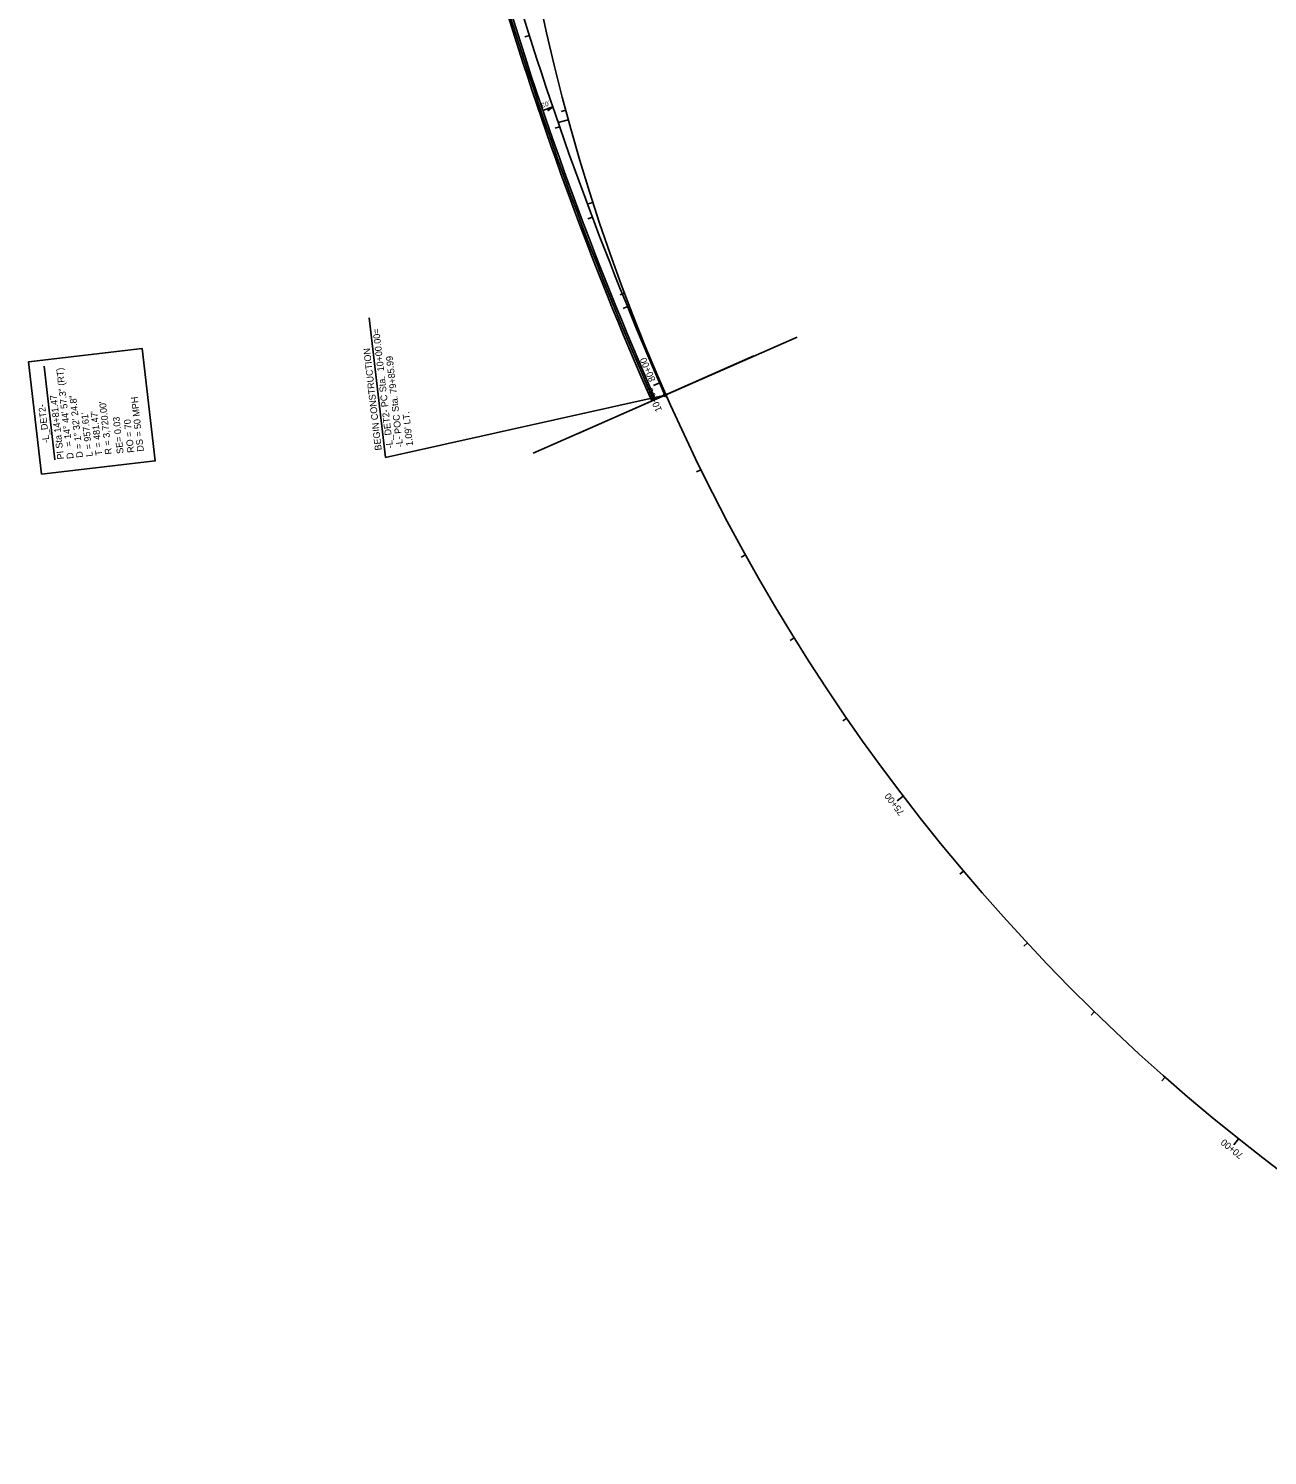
# Model space of a CAD drawing. Extents: x 473658 to 481584, y 489119 to 506230.
# Drawn here: x 477916 to 479205, y 493541 to 495025 of the extents above; entities that cross this region are included whole.
import ezdxf

# ---------------------------------------------------------------- set-up
doc = ezdxf.new("R2010")
doc.units = 0
for name, color, linetype in [('Prop EOT', 7, 'Continuous'), ('Prop Grid Mask', 7, 'Continuous'), ('Prop Horizontal Alignment', 7, 'Continuous'), ('Prop Horizontal Alignment Curve and Spiral Data', 7, 'Continuous'), ('Prop Horizontal Alignment Station Label', 7, 'Continuous'), ('Prop Horizontal Alignment Tick Label', 7, 'Continuous'), ('Prop Horizontal Alignment Tick Large', 7, 'Continuous'), ('Prop Horizontal Alignment Tick Small', 7, 'Continuous'), ('Prop Paved Shoulder', 7, 'Continuous'), ('Prop Superelevation  Arrow CELL', 7, 'Continuous'), ('Prop Superelevation Label', 7, 'Continuous'), ('Scratch_Level_3', 7, 'Continuous'), ('Scratch_Level_4', 7, 'Continuous'), ('Scratch_Level_5', 7, 'Continuous'), ('Scratch_Level_6', 7, 'Continuous'), ('Scratch_Level_9', 7, 'Continuous')]:
    doc.layers.add(name, color=color, linetype=linetype)

msp = doc.modelspace()

# ---------------------------------------------------------------- linework, layer by layer
at = {"layer": 'Prop EOT'}
msp.add_arc((481983.3, 496141.9), 3731, 188.9925, 203.7418, dxfattribs=at)
at = {"layer": 'Prop Grid Mask'}
msp.add_lwpolyline([(477929.8, 494562), (477916.3, 494678.9), (478034.6, 494692.6), (478048.1, 494575.7)], close=True, dxfattribs=at)
at = {"layer": 'Prop Horizontal Alignment'}
for centre, radius, start, end in [((481983.3, 496141.9), 3720, 188.9925, 203.7418), ((480454.8, 495471.8), 2050, 189.8162, 250.3298)]:
    msp.add_arc(centre, radius, start, end, dxfattribs=at)
at = {"layer": 'Prop Horizontal Alignment Station Label'}
for p, q in [((478287.4, 494579.4), (478270.6, 494724.7)), ((477932.4, 494674.2), (477943.7, 494576.8)), ((477932.4, 494674.2), (477943.7, 494576.8)), ((478578.2, 494644.1), (478287.4, 494579.4))]:
    msp.add_line(p, q, dxfattribs=at)
msp.add_circle((478578.2, 494644.1), 1.5, dxfattribs=at)
msp.add_circle((478578.2, 494644.1), 1.5, dxfattribs=at)
at = {"layer": 'Prop Horizontal Alignment Tick Large'}
for p, q in [((478573.6, 494657.4), (478566.2, 494654.2)), ((478578.2, 494644.1), (478570.9, 494640.9)), ((478825.9, 494227.2), (478819.6, 494222.3)), ((479174.7, 493870.7), (479169.7, 493864.4))]:
    msp.add_line(p, q, dxfattribs=at)
at = {"layer": 'Prop Horizontal Alignment Tick Small'}
for p, q in [((478437.1, 495018.2), (478432.3, 495016.7)), ((478474.9, 494940.4), (478470.1, 494939.1)), ((478468.6, 494923.3), (478463.9, 494921.7)), ((478503.2, 494844.5), (478498.4, 494843)), ((478502.6, 494829.3), (478497.9, 494827.5)), ((478536.1, 494750.1), (478531.4, 494748.3)), ((478539.1, 494736.2), (478534.5, 494734.3)), ((478615.5, 494566.6), (478611, 494564.4)), ((478661.8, 494478), (478657.5, 494475.6)), ((478712.4, 494391.8), (478708.2, 494389.1)), ((478767.2, 494308.1), (478763.1, 494305.3)), ((478888.6, 494149.2), (478884.7, 494146)), ((478954.9, 494074.4), (478951.2, 494071)), ((479024.8, 494003), (479021.3, 493999.4)), ((479098.2, 493935), (479094.8, 493931.2))]:
    msp.add_line(p, q, dxfattribs=at)
at = {"layer": 'Prop Paved Shoulder'}
msp.add_arc((481983.3, 496141.9), 3733, 194.2248, 203.7418, dxfattribs=at)
at = {"layer": 'Prop Superelevation  Arrow CELL'}
msp.add_lwpolyline([(478461.5, 494943.8), (478456.5, 494940), (478457.2, 494942.4)], close=True, dxfattribs=at)
at = {"layer": 'Prop Superelevation Label'}
msp.add_line((478451.1, 494940.3), (478461.5, 494943.8), dxfattribs=at)
at = {"layer": 'Scratch_Level_3'}
msp.add_line((478477.5, 494930.3), (478467.1, 494927.5), dxfattribs=at)
at = {"layer": 'Scratch_Level_4'}
msp.add_arc((481983.3, 496141.9), 3735, 188.9925, 203.7418, dxfattribs=at)
at = {"layer": 'Scratch_Level_5'}
msp.add_line((478440.9, 494583.7), (478715.5, 494704.5), dxfattribs=at)
at = {"layer": 'Scratch_Level_6'}
msp.add_line((478467.1, 494927.5), (478477.5, 494930.3), dxfattribs=at)
at = {"layer": 'Scratch_Level_9'}
msp.add_line((478487.7, 494604.2), (478670.7, 494684.9), dxfattribs=at)

# ---------------------------------------------------------------- texts
at = {"layer": 'Prop Horizontal Alignment Curve and Spiral Data'}
for s, rotation, p in [('= 14%%d 44\' 57.3" (RT)', 96.6074, (477961.5, 494591)), ('PI Sta 14+81.47', 96.6074, (477953.3, 494577.7)), ('D = 1%%d 32\' 24.8"', 96.6074, (477973.2, 494579.4)), ("R = 3,720.00'", 96.6074, (478003, 494582.8)), ('DS = 50 MPH', 96.6074, (478036.3, 494585.8)), ("L = 957.61'", 96.6074, (477983.2, 494580.5)), ("T = 481.47'", 96.6074, (477993.1, 494581.7)), ('SE= 0.03', 96.5773, (478015.2, 494583.6)), ('RO = 70', 96.6074, (478026.3, 494584.6)), ('D', 96.6074, (477963.3, 494578.2))]:
    msp.add_text(s, height=7, rotation=rotation, dxfattribs=at).set_placement(p)
at = {"layer": 'Prop Horizontal Alignment Station Label'}
for s, p in [('-L_DET2- PC Sta.  10+00.00=', (478295.4, 494589.2)), ('BEGIN CONSTRUCTION', (478283.6, 494587)), ('-L- POC Sta. 79+85.99', (478305.8, 494590.4)), ('-L_DET2-', (477938, 494594.8)), ('-L_DET2-', (477938, 494594.8)), ("1.09' LT.", (478316.2, 494591.6))]:
    msp.add_text(s, height=7, rotation=96.6074, dxfattribs=at).set_placement(p)
at = {"layer": 'Prop Horizontal Alignment Tick Label'}
for s, rotation, p in [('80+00', 113.4091, (478568.6, 494659.9)), ('10+00', 113.7418, (478575.2, 494628.6)), ('75+00', 127.3837, (478827.5, 494210.3)), ('70+00', 141.3583, (479180.2, 493854.7))]:
    msp.add_text(s, height=7, rotation=rotation, dxfattribs=at).set_placement(p)
at = {"layer": 'Prop Superelevation Label'}
msp.add_text('.03', height=5, rotation=198.7866, dxfattribs=at).set_placement((478457.9, 494950.6))

doc.saveas('drawing.dxf')
